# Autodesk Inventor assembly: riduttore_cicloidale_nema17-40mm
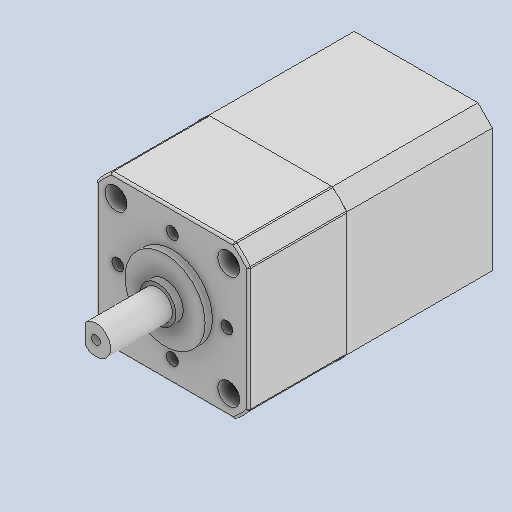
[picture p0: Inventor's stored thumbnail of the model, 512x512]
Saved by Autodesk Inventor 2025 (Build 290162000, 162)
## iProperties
Created: 2026-03
Part Number: riduttore_cicloidale_nema17-40mm
Document SubType Name: Assembly
Designer: R5800u
Author: R5800u
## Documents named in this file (3)
- C:\Users\Ryzen5700u\Desktop\robot_cicloidale_singolo\Workgroups\NotInProject\riduttore_cicloidale_nema17-40mm.iam
- C:\Users\Ryzen5700u\Desktop\robot_cicloidale_singolo\Workgroups\NotInProject\NEMA 17-40mm.ipt
- C:\Users\Ryzen5700u\Desktop\robot_cicloidale_singolo\Workgroups\NotInProject\riduttore ciccloidale TS42 15-1.ipt
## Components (2 placed, 2 different names)
1. NEMA 17-40mm:1 — Coincidente:1, Coincidente:2, Angolo:1
2. riduttore ciccloidale TS42 15-1:1 — Coincidente:1, Coincidente:2, Angolo:1
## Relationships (3: Mate 2, Angle 1)
- Coincidente:1 [Mate]: NEMA 17-40mm:1 ↔ riduttore ciccloidale TS42 15-1:1
- Coincidente:2 [Mate]: NEMA 17-40mm:1 ↔ riduttore ciccloidale TS42 15-1:1
- Angolo:1 [Angle]: NEMA 17-40mm:1 ↔ riduttore ciccloidale TS42 15-1:1
